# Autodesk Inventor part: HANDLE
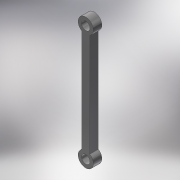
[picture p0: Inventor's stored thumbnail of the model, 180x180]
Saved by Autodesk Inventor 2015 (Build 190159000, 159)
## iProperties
Created: 2014-08
Part Number: HANDLE
Material: Steel, Mild
Document SubType Name: Modeling
Designer: lakshayg
Density: 7.85 g/cm^3
Appearance: Semi-Polished
Mass: 234.322 g
Surface Area: 110.431 cm^2
Volume: 29.8499 cm^3
Author: lakshayg
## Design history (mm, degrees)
sketch "Sketch1"
  geometry: L1 (0, 0)-(0, -171.433); L2 (-6, -9.516)-(-6, -161.916); L3 (6, -9.516)-(6, -161.916); C1 r 6.25 at (0, 0); C2 r 6.25 at (0, -171.433); A1 r 11.25 centre (0, -171.433) between (-10.189, -176.201) and (6, -161.916); A2 r 11.25 centre (0, 0) between (6, -9.516) and (11.124, 1.677); A3 r 11.25 centre (0, -171.433) between (-6, -161.916) and (-10.189, -176.201); A4 r 11.25 centre (0, 0) between (11.124, 1.677) and (-6, -9.516); 2 further points
  constraints: 8 point on circle, 6 centre point, 6 end point, 5 coincident, 2 parallel, 1 equal radius, 1 point on line, 1 vertical, 1 other
  dimensions: "d6" = 12 distance between parallel lines of L2 L3; "d7" = 152.4 distance of L3.start L3.end; "d9" = 12.5 diameter of C1
extrude "Extrusion1" new body sketch "Sketch1" distance "d4" = 12.7; taper "d5" = 0 deg
body "Solid1"
other parameters: "d8" = 5
